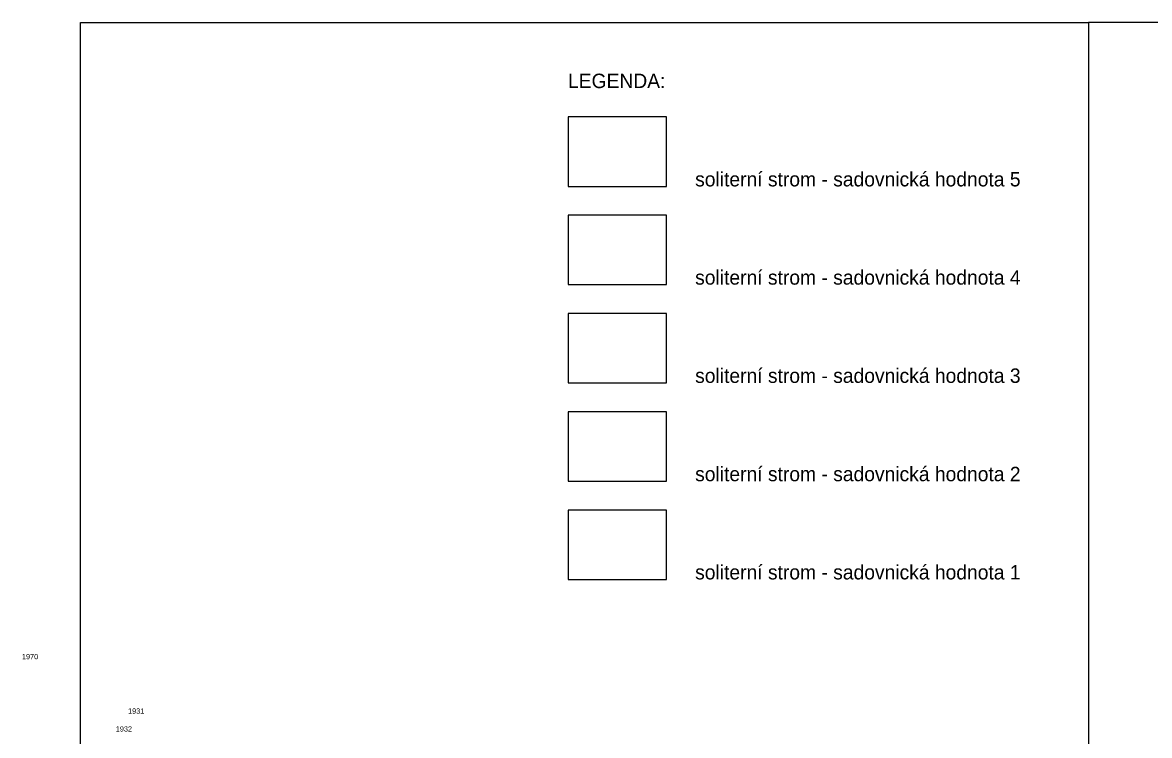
# Model space of a CAD drawing. Extents: x -740053 to -737517, y -1033516 to -1032465.
# Drawn here: x -738281.5 to -738164.2, y -1032539 to -1032464.7 of the extents above; entities that cross this region are included whole.
import ezdxf

# ---------------------------------------------------------------- set-up
doc = ezdxf.new("R2010")
doc.units = 0
for name, color, linetype in [('bod-cislo', 7, 'Continuous'), ('Predmety bez rozlišeni', 7, 'Continuous'), ('promika-formát', 7, 'Continuous')]:
    doc.layers.add(name, color=color, linetype=linetype)

msp = doc.modelspace()

# ---------------------------------------------------------------- linework, layer by layer
at = {"layer": 'Predmety bez rozlišeni'}
for p, q in [((-738275.5, -1032613.21), (-738275.5, -1032464.71)), ((-738275.5, -1032613.21), (-738275.5, -1032464.71)), ((-738275.5, -1032464.71), (-738170.5, -1032464.71))]:
    msp.add_line(p, q, dxfattribs=at)
for points in [[(-738224.71, -1032481.78), (-738214.47, -1032481.78), (-738214.47, -1032474.54), (-738224.71, -1032474.54)], [(-738224.71, -1032492.01), (-738214.47, -1032492.01), (-738214.47, -1032484.78), (-738224.71, -1032484.78)], [(-738224.71, -1032502.24), (-738214.47, -1032502.24), (-738214.47, -1032495.01), (-738224.71, -1032495.01)], [(-738224.71, -1032512.48), (-738214.47, -1032512.48), (-738214.47, -1032505.24), (-738224.71, -1032505.24)], [(-738224.71, -1032522.71), (-738214.47, -1032522.71), (-738214.47, -1032515.48), (-738224.71, -1032515.48)]]:
    msp.add_lwpolyline(points, close=True, dxfattribs=at)
at = {"layer": 'promika-formát'}
msp.add_lwpolyline([(-738170.5, -1032613.21), (-738065.5, -1032613.21), (-738065.5, -1032464.71), (-738170.5, -1032464.71)], close=True, dxfattribs=at)

# ---------------------------------------------------------------- texts
at = {"layer": 'bod-cislo'}
for s, p in [('1970', (-738281.58, -1032531.02)), ('1931', (-738270.53, -1032536.69)), ('1932', (-738271.81, -1032538.55))]:
    msp.add_text(s, height=0.55, dxfattribs=at).set_placement(p)
at = {"layer": 'Predmety bez rozlišeni'}
for s, p in [('LEGENDA:', (-738224.71, -1032471.54)), ('soliterní strom - sadovnická hodnota 5', (-738211.47, -1032481.78)), ('soliterní strom - sadovnická hodnota 4', (-738211.47, -1032492.01)), ('soliterní strom - sadovnická hodnota 3', (-738211.47, -1032502.24)), ('soliterní strom - sadovnická hodnota 2 ', (-738211.47, -1032512.48)), ('soliterní strom - sadovnická hodnota 1', (-738211.47, -1032522.71))]:
    msp.add_text(s, height=1.5, dxfattribs=at).set_placement(p)

doc.saveas('drawing.dxf')
